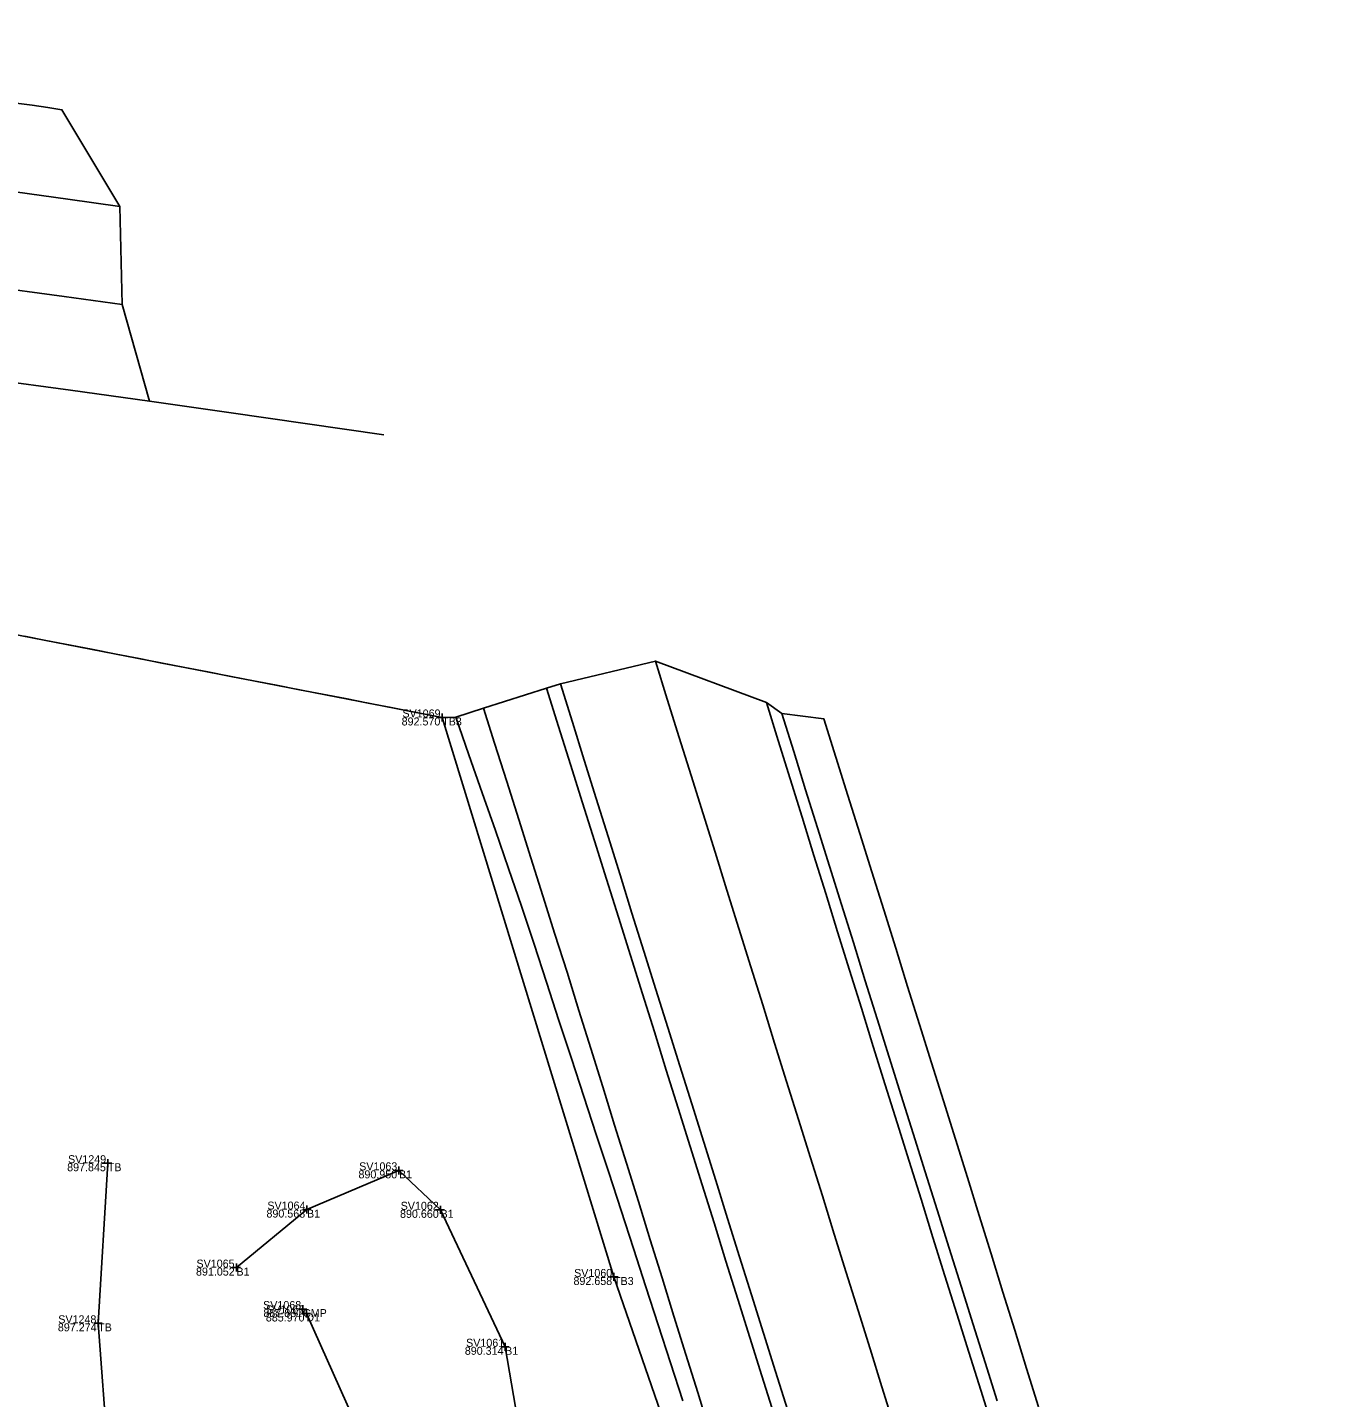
# Model space of a CAD drawing. Extents: x 1918148 to 1919797, y 624701 to 627089.
# Drawn here: x 1919148.9 to 1919311.1, y 625706.2 to 625877.4 of the extents above; entities that cross this region are included whole.
import ezdxf

# ---------------------------------------------------------------- set-up
doc = ezdxf.new("R2010")
doc.units = 0
for name, color, linetype in [('DR_X_Ditch', 7, 'Continuous'), ('DT_X_Break_Line', 7, 'Continuous'), ('DT_X_Terrain_Boundary', 7, 'Continuous'), ('PM_X_Channelizing_Line', 7, 'Continuous'), ('PM_X_CL_Double_Solid', 7, 'Continuous'), ('PM_X_Edge_Line', 7, 'Continuous'), ('PM_X_Lane_Line', 7, 'Continuous'), ('PV_X_EOP', 7, 'Continuous'), ('PV_X_Shoulder_Aggregate', 7, 'Continuous'), ('PV_X_Shoulder_Rumble_Strip', 7, 'Continuous'), ('SV_X_Break_Lines', 7, 'Continuous'), ('SV_X_Shot_Marker', 7, 'Continuous'), ('SV_X_Text_Comment', 7, 'Continuous'), ('SV_X_Text_Elevation', 7, 'Continuous'), ('SV_X_Text_Name', 7, 'Continuous'), ('SV_X_Top_of_Bank', 7, 'Continuous')]:
    doc.layers.add(name, color=color, linetype=linetype)

msp = doc.modelspace()

# ---------------------------------------------------------------- linework, layer by layer
at = {"layer": 'DR_X_Ditch'}
msp.add_lwpolyline([(1919215.15, 625628.65), (1919210.09, 625633.68), (1919204.01, 625653.25), (1919199.4, 625670.45), (1919194.75, 625692.02), (1919183.69, 625716.71)], dxfattribs=at)
at = {"layer": 'DT_X_Break_Line'}
msp.add_lwpolyline([(1919148.49, 625801.31), (1919151.35, 625800.75), (1919154.22, 625800.2), (1919157.08, 625799.64), (1919159.94, 625799.08), (1919162.8, 625798.53), (1919165.66, 625797.97), (1919168.53, 625797.41), (1919171.39, 625796.86), (1919174.25, 625796.3), (1919177.11, 625795.74), (1919179.97, 625795.19), (1919182.84, 625794.63), (1919185.7, 625794.08), (1919188.56, 625793.52), (1919191.42, 625792.96), (1919194.28, 625792.41), (1919197.15, 625791.85), (1919200.01, 625791.29), (1919200.65, 625791.17)], dxfattribs=at)
at = {"layer": 'DT_X_Terrain_Boundary'}
for points in [[(1919144.31, 625833.4), (1919154.22, 625832.06), (1919164.12, 625830.68), (1919160.7, 625842.77), (1919160.39, 625855.01), (1919153.16, 625867.09), (1919151.42, 625867.35), (1919149.44, 625867.64), (1919147.46, 625867.92)], [(1919275.12, 625705.06), (1919273.64, 625709.83), (1919272.16, 625714.61), (1919270.68, 625719.38), (1919269.2, 625724.16), (1919267.72, 625728.94), (1919266.24, 625733.71), (1919264.76, 625738.49), (1919263.26, 625743.26), (1919261.77, 625748.03), (1919260.28, 625752.8), (1919258.78, 625757.57), (1919257.29, 625762.35), (1919255.8, 625767.12), (1919254.3, 625771.89), (1919252.81, 625776.66), (1919251.32, 625781.43), (1919249.82, 625786.2), (1919248.33, 625790.98), (1919243.06, 625791.68), (1919241.14, 625793.04), (1919227.28, 625798.22), (1919215.42, 625795.38), (1919213.67, 625794.82), (1919205.81, 625792.34), (1919202.35, 625791.2), (1919200.65, 625791.17), (1919111.29, 625808.54)]]:
    msp.add_lwpolyline(points, dxfattribs=at)
at = {"layer": 'PM_X_Channelizing_Line'}
msp.add_lwpolyline([(1918955.09, 625877.37), (1918965.06, 625876.6), (1918975.03, 625875.79), (1918984.99, 625874.95), (1918994.95, 625874.08), (1919004.91, 625873.18), (1919014.87, 625872.24), (1919024.82, 625871.28), (1919034.77, 625870.28), (1919044.72, 625869.26), (1919054.67, 625868.2), (1919064.61, 625867.11), (1919074.54, 625865.99), (1919084.48, 625864.84), (1919094.41, 625863.66), (1919104.33, 625862.45), (1919114.25, 625861.2), (1919124.17, 625859.93), (1919134.09, 625858.62), (1919144, 625857.29), (1919153.9, 625855.92), (1919160.39, 625855.01)], dxfattribs=at)
at = {"layer": 'PM_X_CL_Double_Solid'}
msp.add_lwpolyline([(1918954.64, 625865.34), (1918964.6, 625864.53), (1918974.57, 625863.69), (1918984.53, 625862.82), (1918994.49, 625861.93), (1919004.45, 625861), (1919014.4, 625860.05), (1919024.35, 625859.07), (1919034.3, 625858.06), (1919044.25, 625857.03), (1919054.19, 625855.96), (1919064.13, 625854.87), (1919074.07, 625853.75), (1919084, 625852.6), (1919093.93, 625851.42), (1919103.86, 625850.22), (1919113.79, 625848.98), (1919123.71, 625847.72), (1919133.62, 625846.43), (1919143.53, 625845.11), (1919153.44, 625843.77), (1919160.7, 625842.77)], dxfattribs=at)
at = {"layer": 'PM_X_Edge_Line'}
for points in [[(1919147.46, 625867.92), (1919149.44, 625867.64), (1919151.42, 625867.35), (1919153.16, 625867.09)], [(1919215.42, 625795.38), (1919216.91, 625790.6), (1919218.39, 625785.83), (1919219.88, 625781.06), (1919221.37, 625776.28), (1919222.86, 625771.51), (1919224.34, 625766.74), (1919225.83, 625761.96), (1919227.33, 625757.19), (1919228.83, 625752.42), (1919230.32, 625747.65), (1919231.82, 625742.88), (1919233.31, 625738.11), (1919234.81, 625733.34), (1919236.3, 625728.56), (1919237.8, 625723.79), (1919239.29, 625719.02), (1919240.79, 625714.25), (1919242.28, 625709.48), (1919243.78, 625704.71)], [(1919241.14, 625793.04), (1919242.63, 625788.27), (1919244.11, 625783.49), (1919245.59, 625778.72), (1919247.07, 625773.94), (1919248.55, 625769.16), (1919250.03, 625764.39), (1919251.51, 625759.61), (1919253, 625754.84), (1919254.48, 625750.06), (1919255.96, 625745.29), (1919257.46, 625740.52), (1919258.95, 625735.75), (1919260.45, 625730.97), (1919261.94, 625726.2), (1919263.44, 625721.43), (1919264.93, 625716.66), (1919266.43, 625711.89), (1919267.92, 625707.12), (1919269.42, 625702.35)]]:
    msp.add_lwpolyline(points, dxfattribs=at)
at = {"layer": 'PM_X_Lane_Line'}
for points in [[(1918955.39, 625853.42), (1918965.36, 625852.63), (1918975.33, 625851.81), (1918985.29, 625850.96), (1918995.25, 625850.08), (1919005.21, 625849.17), (1919015.17, 625848.23), (1919025.12, 625847.27), (1919035.07, 625846.27), (1919045.02, 625845.25), (1919054.96, 625844.19), (1919064.9, 625843.11), (1919074.84, 625842), (1919084.78, 625840.86), (1919094.71, 625839.69), (1919104.63, 625838.49), (1919114.56, 625837.26), (1919124.48, 625836), (1919134.4, 625834.72), (1919144.31, 625833.4), (1919154.22, 625832.06), (1919164.12, 625830.68), (1919174.03, 625829.28), (1919193.35, 625826.46)], [(1919227.28, 625798.22), (1919228.77, 625793.45), (1919230.26, 625788.67), (1919231.75, 625783.9), (1919233.24, 625779.13), (1919234.73, 625774.35), (1919236.22, 625769.58), (1919237.71, 625764.81), (1919239.2, 625760.03), (1919240.68, 625755.26), (1919242.17, 625750.49), (1919243.66, 625745.71), (1919245.15, 625740.94), (1919246.64, 625736.17), (1919248.13, 625731.39), (1919249.62, 625726.62), (1919251.1, 625721.85), (1919252.59, 625717.07), (1919254.08, 625712.3), (1919255.57, 625707.53), (1919257.06, 625702.75)]]:
    msp.add_lwpolyline(points, dxfattribs=at)
at = {"layer": 'PV_X_EOP'}
for points in [[(1919234.05, 625702.05), (1919232.57, 625706.82), (1919231.08, 625711.6), (1919229.6, 625716.37), (1919228.12, 625721.15), (1919226.63, 625725.92), (1919225.15, 625730.7), (1919223.66, 625735.47), (1919222.18, 625740.25), (1919220.7, 625745.02), (1919219.21, 625749.8), (1919217.73, 625754.57), (1919216.25, 625759.35), (1919214.74, 625764.11), (1919213.24, 625768.88), (1919211.73, 625773.65), (1919210.22, 625778.42), (1919208.71, 625783.18), (1919207.2, 625787.95), (1919205.81, 625792.34)], [(1919248.33, 625790.98), (1919249.82, 625786.2), (1919251.32, 625781.43), (1919252.81, 625776.66), (1919254.3, 625771.89), (1919255.8, 625767.12), (1919257.29, 625762.35), (1919258.78, 625757.57), (1919260.28, 625752.8), (1919261.77, 625748.03), (1919263.26, 625743.26), (1919264.76, 625738.49), (1919266.24, 625733.71), (1919267.72, 625728.94), (1919269.2, 625724.16), (1919270.68, 625719.38), (1919272.16, 625714.61), (1919273.64, 625709.83), (1919275.12, 625705.06)]]:
    msp.add_lwpolyline(points, dxfattribs=at)
at = {"layer": 'PV_X_Shoulder_Aggregate'}
msp.add_lwpolyline([(1919202.35, 625791.2), (1919204, 625786.48), (1919205.65, 625781.76), (1919207.3, 625777.04), (1919208.95, 625772.32), (1919210.56, 625767.58), (1919212.12, 625762.83), (1919213.67, 625758.08), (1919215.23, 625753.33), (1919216.79, 625748.58), (1919218.35, 625743.83), (1919219.9, 625739.08), (1919221.46, 625734.33), (1919223.01, 625729.57), (1919224.54, 625724.81), (1919226.08, 625720.05), (1919227.62, 625715.3), (1919229.15, 625710.54), (1919230.69, 625705.78)], dxfattribs=at)
at = {"layer": 'PV_X_Shoulder_Rumble_Strip'}
for points in [[(1919213.67, 625794.82), (1919215.17, 625790.05), (1919216.67, 625785.28), (1919218.17, 625780.51), (1919219.67, 625775.74), (1919221.18, 625770.98), (1919222.68, 625766.21), (1919224.18, 625761.44), (1919225.67, 625756.66), (1919227.15, 625751.89), (1919228.64, 625747.12), (1919230.13, 625742.34), (1919231.62, 625737.57), (1919233.11, 625732.8), (1919234.6, 625728.03), (1919236.09, 625723.25), (1919237.58, 625718.48), (1919239.07, 625713.71), (1919240.56, 625708.93), (1919242.05, 625704.16)], [(1919243.06, 625791.68), (1919244.55, 625786.91), (1919246.04, 625782.14), (1919247.53, 625777.37), (1919249.02, 625772.59), (1919250.51, 625767.82), (1919252, 625763.05), (1919253.49, 625758.28), (1919254.98, 625753.5), (1919256.47, 625748.73), (1919257.96, 625743.96), (1919259.46, 625739.19), (1919260.96, 625734.42), (1919262.46, 625729.65), (1919263.96, 625724.88), (1919265.45, 625720.11), (1919266.95, 625715.34), (1919268.45, 625710.57), (1919269.95, 625705.8)]]:
    msp.add_lwpolyline(points, dxfattribs=at)
at = {"layer": 'SV_X_Break_Lines'}
msp.add_lwpolyline([(1919234.64, 625621.64), (1919229.55, 625636.85), (1919222.35, 625651.15), (1919214.84, 625675.55), (1919208.51, 625712.55), (1919200.45, 625729.66), (1919195.26, 625734.59), (1919183.77, 625729.69), (1919174.96, 625722.44)], dxfattribs=at)
at = {"layer": 'SV_X_Shot_Marker'}
for p, q in [((1919200.15, 625791.17), (1919201.15, 625791.17)), ((1919200.65, 625791.67), (1919200.65, 625790.67)), ((1919200.65, 625791.17), (1919200.65, 625791.17)), ((1919158.39, 625735.48), (1919159.39, 625735.48)), ((1919158.89, 625735.98), (1919158.89, 625734.98)), ((1919158.89, 625735.48), (1919158.89, 625735.48)), ((1919194.76, 625734.59), (1919195.76, 625734.59)), ((1919195.26, 625735.09), (1919195.26, 625734.09)), ((1919195.26, 625734.59), (1919195.26, 625734.59)), ((1919183.27, 625729.69), (1919184.27, 625729.69)), ((1919183.77, 625730.19), (1919183.77, 625729.19)), ((1919183.77, 625729.69), (1919183.77, 625729.69)), ((1919199.95, 625729.66), (1919200.95, 625729.66)), ((1919200.45, 625730.16), (1919200.45, 625729.16)), ((1919200.45, 625729.66), (1919200.45, 625729.66)), ((1919174.46, 625722.44), (1919175.46, 625722.44)), ((1919174.96, 625722.94), (1919174.96, 625721.94)), ((1919174.96, 625722.44), (1919174.96, 625722.44)), ((1919221.61, 625721.27), (1919222.61, 625721.27)), ((1919222.11, 625721.77), (1919222.11, 625720.77)), ((1919222.11, 625721.27), (1919222.11, 625721.27)), ((1919183.27, 625717.76), (1919183.27, 625716.76)), ((1919157.69, 625715.98), (1919157.69, 625714.98)), ((1919182.77, 625717.26), (1919183.77, 625717.26)), ((1919183.19, 625716.71), (1919184.19, 625716.71)), ((1919183.27, 625717.26), (1919183.27, 625717.26)), ((1919183.69, 625717.21), (1919183.69, 625716.21)), ((1919183.69, 625716.71), (1919183.69, 625716.71)), ((1919157.19, 625715.48), (1919158.19, 625715.48)), ((1919157.69, 625715.48), (1919157.69, 625715.48)), ((1919208.01, 625712.55), (1919209.01, 625712.55)), ((1919208.51, 625713.05), (1919208.51, 625712.05)), ((1919208.51, 625712.55), (1919208.51, 625712.55))]:
    msp.add_line(p, q, dxfattribs=at)
at = {"layer": 'SV_X_Top_of_Bank'}
for points in [[(1919311.1, 625448.91), (1919294.98, 625498.61), (1919274.7, 625559.01), (1919260.24, 625603.73), (1919254.49, 625621.03), (1919244.11, 625659.16), (1919235.03, 625683.79), (1919222.11, 625721.27), (1919200.65, 625791.17)], [(1919008.68, 625701.6), (1919017.73, 625687.93), (1919021.83, 625676.64), (1919027.22, 625671.33), (1919042.19, 625668.18), (1919068.63, 625667.59), (1919096.2, 625663.51), (1919124.68, 625660.31), (1919151.38, 625658.36), (1919165.45, 625659.92), (1919167.97, 625668.32), (1919163.99, 625682.32), (1919158.88, 625699.33), (1919157.69, 625715.48), (1919158.89, 625735.48)]]:
    msp.add_lwpolyline(points, dxfattribs=at)

# ---------------------------------------------------------------- texts
at = {"layer": 'SV_X_Text_Comment'}
for s, p in [('TB3', (1919200.65, 625790.17)), ('TB', (1919158.89, 625734.48)), ('B1', (1919195.26, 625733.59)), ('B1', (1919183.77, 625728.69)), ('B1', (1919200.45, 625728.66)), ('B1', (1919174.96, 625721.44)), ('TB3', (1919222.11, 625720.27)), ('CMP', (1919183.27, 625716.26)), ('D1', (1919183.69, 625715.71)), ('TB', (1919157.69, 625714.48)), ('B1', (1919208.51, 625711.55))]:
    msp.add_text(s, height=1, dxfattribs=at).set_placement(p)
at = {"layer": 'SV_X_Text_Elevation'}
for s, p in [('892.570', (1919195.59, 625790.17)), ('897.845', (1919153.82, 625734.48)), ('890.950', (1919190.2, 625733.59)), ('890.568', (1919178.71, 625728.69)), ('890.660', (1919195.39, 625728.66)), ('891.052', (1919169.91, 625721.44)), ('892.658', (1919217.05, 625720.27)), ('887.881', (1919178.33, 625716.26)), ('885.970', (1919178.63, 625715.71)), ('897.274', (1919152.66, 625714.48)), ('890.314', (1919203.48, 625711.55))]:
    msp.add_text(s, height=1, dxfattribs=at).set_placement(p)
at = {"layer": 'SV_X_Text_Name'}
for s, p in [('SV1069', (1919195.69, 625791.17)), ('SV1249', (1919153.93, 625735.48)), ('SV1063', (1919190.29, 625734.59)), ('SV1064', (1919178.82, 625729.69)), ('SV1062', (1919195.47, 625729.66)), ('SV1065', (1919169.97, 625722.44)), ('SV1060', (1919217.13, 625721.27)), ('SV1068', (1919178.29, 625717.26)), ('SV1067', (1919178.67, 625716.71)), ('SV1248', (1919152.71, 625715.48)), ('SV1061', (1919203.64, 625712.55))]:
    msp.add_text(s, height=1, dxfattribs=at).set_placement(p)

doc.saveas('drawing.dxf')
